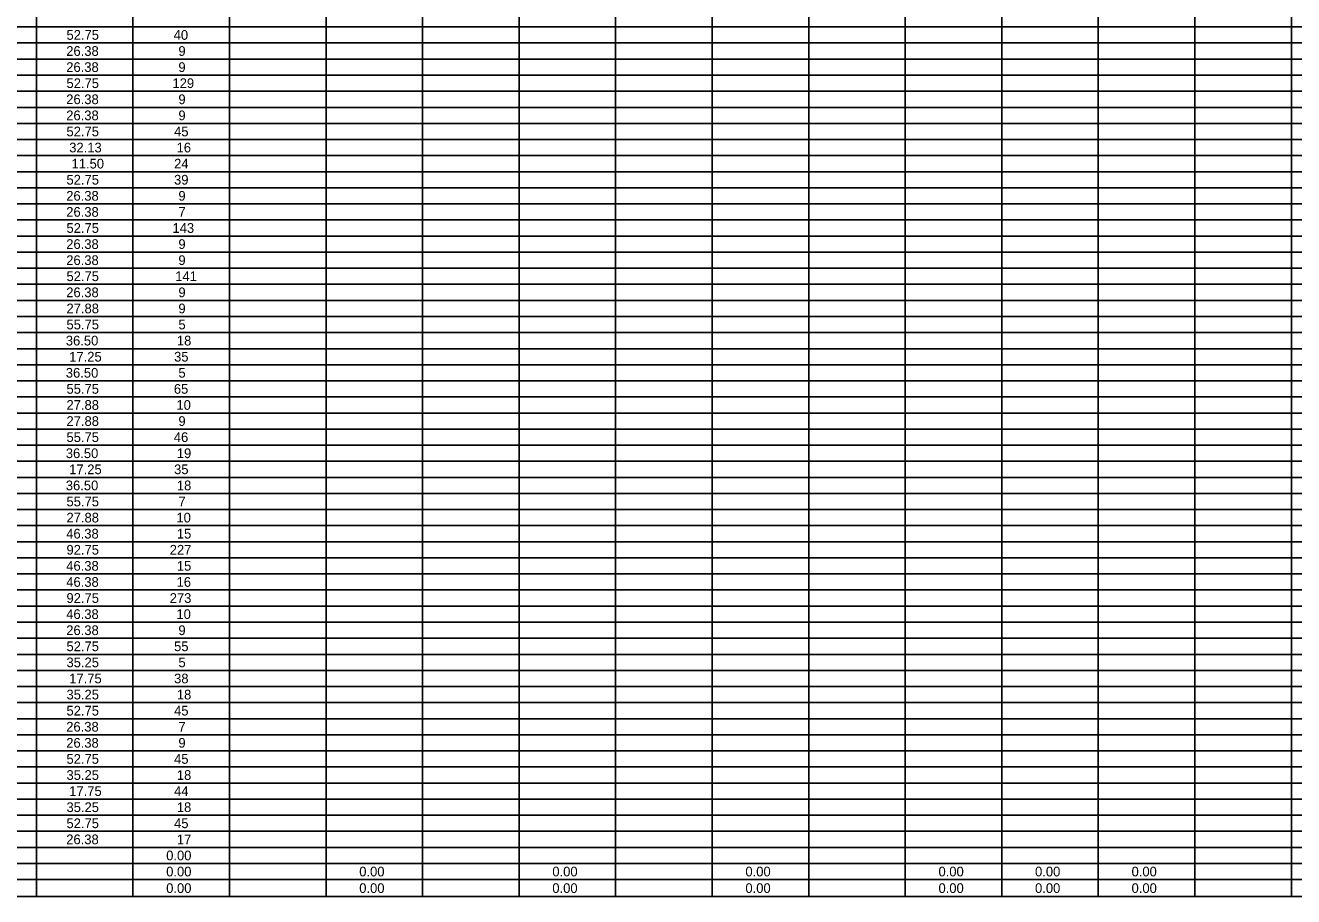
# Model space of a CAD drawing. Extents: x 1226590 to 1228573, y 151304 to 154224.
# Drawn here: x 1226976 to 1227629, y 153323 to 153772 of the extents above; entities that cross this region are included whole.
import ezdxf

# ---------------------------------------------------------------- set-up
doc = ezdxf.new("R2010")
doc.units = 0
doc.layers.add('R_Dimension', color=7, linetype='Continuous')

msp = doc.modelspace()

# ---------------------------------------------------------------- linework, layer by layer
at = {"layer": 'R_Dimension'}
for p, q in [((1226981.73, 153323.28), (1226981.73, 153928.75)), ((1227031.46, 153323.28), (1227031.46, 153928.75)), ((1227081.18, 153323.28), (1227081.18, 153928.75)), ((1227130.91, 153323.28), (1227130.91, 153928.75)), ((1227180.63, 153323.28), (1227180.63, 153928.75)), ((1227230.36, 153323.28), (1227230.36, 153928.75)), ((1227280.08, 153323.28), (1227280.08, 153928.75)), ((1227329.81, 153323.28), (1227329.81, 153928.75)), ((1227379.53, 153323.28), (1227379.53, 153928.75)), ((1227429.26, 153323.28), (1227429.26, 153928.75)), ((1227478.98, 153323.28), (1227478.98, 153928.75)), ((1227528.71, 153323.28), (1227528.71, 153928.75)), ((1227578.43, 153323.28), (1227578.43, 153928.75)), ((1227628.16, 153323.28), (1227628.16, 153928.75)), ((1226590.27, 153771.29), (1228572.93, 153771.29)), ((1226590.27, 153763), (1228572.93, 153763)), ((1226590.27, 153754.72), (1228572.93, 153754.72)), ((1226590.27, 153746.43), (1228572.93, 153746.43)), ((1226590.27, 153738.14), (1228572.93, 153738.14)), ((1226590.27, 153729.85), (1228572.93, 153729.85)), ((1226590.27, 153721.57), (1228572.93, 153721.57)), ((1226590.27, 153713.28), (1228572.93, 153713.28)), ((1226590.27, 153704.99), (1228572.93, 153704.99)), ((1226590.27, 153696.7), (1228572.93, 153696.7)), ((1226590.27, 153688.42), (1228572.93, 153688.42)), ((1226590.27, 153680.13), (1228572.93, 153680.13)), ((1226590.27, 153671.84), (1228572.93, 153671.84)), ((1226590.27, 153663.55), (1228572.93, 153663.55)), ((1226590.27, 153655.27), (1228572.93, 153655.27)), ((1226590.27, 153646.98), (1228572.93, 153646.98)), ((1226590.27, 153638.69), (1228572.93, 153638.69)), ((1226590.27, 153630.4), (1228572.93, 153630.4)), ((1226590.27, 153622.12), (1228572.93, 153622.12)), ((1226590.27, 153613.83), (1228572.93, 153613.83)), ((1226590.27, 153605.54), (1228572.93, 153605.54)), ((1226590.27, 153597.25), (1228572.93, 153597.25)), ((1226590.27, 153588.97), (1228572.93, 153588.97)), ((1226590.27, 153580.68), (1228572.93, 153580.68)), ((1226590.27, 153572.39), (1228572.93, 153572.39)), ((1226590.27, 153564.1), (1228572.93, 153564.1)), ((1226590.27, 153555.82), (1228572.93, 153555.82)), ((1226590.27, 153547.53), (1228572.93, 153547.53)), ((1226590.27, 153539.24), (1228572.93, 153539.24)), ((1226590.27, 153530.95), (1228572.93, 153530.95)), ((1226590.27, 153522.67), (1228572.93, 153522.67)), ((1226590.27, 153514.38), (1228572.93, 153514.38)), ((1226590.27, 153506.09), (1228572.93, 153506.09)), ((1226590.27, 153497.8), (1228572.93, 153497.8)), ((1226590.27, 153489.52), (1228572.93, 153489.52)), ((1226590.27, 153481.23), (1228572.93, 153481.23)), ((1226590.27, 153472.94), (1228572.93, 153472.94)), ((1226590.27, 153464.65), (1228572.93, 153464.65)), ((1226590.27, 153456.37), (1228572.93, 153456.37)), ((1226590.27, 153448.08), (1228572.93, 153448.08)), ((1226590.27, 153439.79), (1228572.93, 153439.79)), ((1226590.27, 153431.5), (1228572.93, 153431.5)), ((1226590.27, 153423.22), (1228572.93, 153423.22)), ((1226590.27, 153414.93), (1228572.93, 153414.93)), ((1226590.27, 153406.64), (1228572.93, 153406.64)), ((1226590.27, 153398.35), (1228572.93, 153398.35)), ((1226590.27, 153390.07), (1228572.93, 153390.07)), ((1226590.27, 153381.78), (1228572.93, 153381.78)), ((1226590.27, 153373.49), (1228572.93, 153373.49)), ((1226590.27, 153365.2), (1228572.93, 153365.2)), ((1226590.27, 153356.92), (1228572.93, 153356.92)), ((1226590.27, 153348.63), (1228572.93, 153348.63)), ((1226590.27, 153340.34), (1228572.93, 153340.34)), ((1226590.27, 153332.05), (1228572.93, 153332.05)), ((1226590.27, 153323.28), (1228572.93, 153323.28))]:
    msp.add_line(p, q, dxfattribs=at)

# ---------------------------------------------------------------- texts
for s, p in [('52.75', (1226997.23, 153764.65)), ('40', (1227052.44, 153764.65)), ('26.38', (1226997.11, 153756.36)), ('9', (1227054.88, 153756.36)), ('26.38', (1226997.11, 153748.07)), ('9', (1227054.88, 153748.07)), ('52.75', (1226997.23, 153739.79)), ('129', (1227051.81, 153739.79)), ('26.38', (1226997.11, 153731.5)), ('9', (1227054.88, 153731.5)), ('26.38', (1226997.11, 153723.21)), ('9', (1227054.88, 153723.21)), ('52.75', (1226997.23, 153714.92)), ('45', (1227052.66, 153714.92)), ('32.13', (1226998.64, 153706.64)), ('16', (1227053.94, 153706.64)), ('11.50', (1226999.84, 153698.35)), ('24', (1227052.66, 153698.35)), ('52.75', (1226997.23, 153690.06)), ('39', (1227052.64, 153690.06)), ('26.38', (1226997.11, 153681.77)), ('9', (1227054.88, 153681.77)), ('26.38', (1226997.11, 153673.49)), ('7', (1227054.9, 153673.49)), ('52.75', (1226997.23, 153665.2)), ('143', (1227051.83, 153665.2)), ('26.38', (1226997.11, 153656.91)), ('9', (1227054.88, 153656.91)), ('26.38', (1226997.11, 153648.62)), ('9', (1227054.88, 153648.62)), ('52.75', (1226997.23, 153640.34)), ('141', (1227053.25, 153640.34)), ('26.38', (1226997.11, 153632.05)), ('9', (1227054.88, 153632.05)), ('27.88', (1226997.23, 153623.76)), ('9', (1227054.88, 153623.76)), ('55.75', (1226997.23, 153615.47)), ('5', (1227054.9, 153615.47)), ('36.50', (1226996.89, 153607.19)), ('18', (1227054.08, 153607.19)), ('17.25', (1226998.64, 153598.9)), ('35', (1227052.66, 153598.9)), ('36.50', (1226996.89, 153590.61)), ('5', (1227054.9, 153590.61)), ('55.75', (1226997.23, 153582.32)), ('65', (1227052.54, 153582.32)), ('27.88', (1226997.23, 153574.04)), ('10', (1227053.86, 153574.04)), ('27.88', (1226997.23, 153565.75)), ('9', (1227054.88, 153565.75)), ('55.75', (1226997.23, 153557.46)), ('46', (1227052.52, 153557.46)), ('36.50', (1226996.89, 153549.17)), ('19', (1227054.06, 153549.17)), ('17.25', (1226998.64, 153540.89)), ('35', (1227052.66, 153540.89)), ('36.50', (1226996.89, 153532.6)), ('18', (1227054.08, 153532.6)), ('55.75', (1226997.23, 153524.31)), ('7', (1227054.9, 153524.31)), ('27.88', (1226997.23, 153516.02)), ('10', (1227053.86, 153516.02)), ('46.38', (1226997.11, 153507.74)), ('15', (1227054.08, 153507.74)), ('92.75', (1226997.23, 153499.45)), ('227', (1227050.41, 153499.45)), ('46.38', (1226997.11, 153491.16)), ('15', (1227054.08, 153491.16)), ('46.38', (1226997.11, 153482.87)), ('16', (1227053.94, 153482.87)), ('92.75', (1226997.23, 153474.59)), ('273', (1227050.41, 153474.59)), ('46.38', (1226997.11, 153466.3)), ('10', (1227053.86, 153466.3)), ('26.38', (1226997.11, 153458.01)), ('9', (1227054.88, 153458.01)), ('52.75', (1226997.23, 153449.72)), ('55', (1227052.66, 153449.72)), ('35.25', (1226997.23, 153441.44)), ('5', (1227054.9, 153441.44)), ('17.75', (1226998.64, 153433.15)), ('38', (1227052.66, 153433.15)), ('35.25', (1226997.23, 153424.86)), ('18', (1227054.08, 153424.86)), ('52.75', (1226997.23, 153416.57)), ('45', (1227052.66, 153416.57)), ('26.38', (1226997.11, 153408.29)), ('7', (1227054.9, 153408.29)), ('26.38', (1226997.11, 153400)), ('9', (1227054.88, 153400)), ('52.75', (1226997.23, 153391.71)), ('45', (1227052.66, 153391.71)), ('35.25', (1226997.23, 153383.42)), ('18', (1227054.08, 153383.42)), ('17.75', (1226998.64, 153375.14)), ('44', (1227052.66, 153375.14)), ('35.25', (1226997.23, 153366.85)), ('18', (1227054.08, 153366.85)), ('52.75', (1226997.23, 153358.56)), ('45', (1227052.66, 153358.56)), ('26.38', (1226997.11, 153350.27)), ('17', (1227054.08, 153350.27)), ('0.00', (1227048.58, 153341.99)), ('0.00', (1227048.58, 153333.7)), ('0.00', (1227148.03, 153333.7)), ('0.00', (1227247.48, 153333.7)), ('0.00', (1227346.93, 153333.7)), ('0.00', (1227446.38, 153333.7)), ('0.00', (1227496.11, 153333.7)), ('0.00', (1227545.83, 153333.7)), ('0.00', (1227048.58, 153325.17)), ('0.00', (1227148.03, 153325.17)), ('0.00', (1227247.48, 153325.17)), ('0.00', (1227346.93, 153325.17)), ('0.00', (1227446.38, 153325.17)), ('0.00', (1227496.11, 153325.17)), ('0.00', (1227545.83, 153325.17))]:
    msp.add_text(s, height=5, dxfattribs=at).set_placement(p)

doc.saveas('drawing.dxf')
